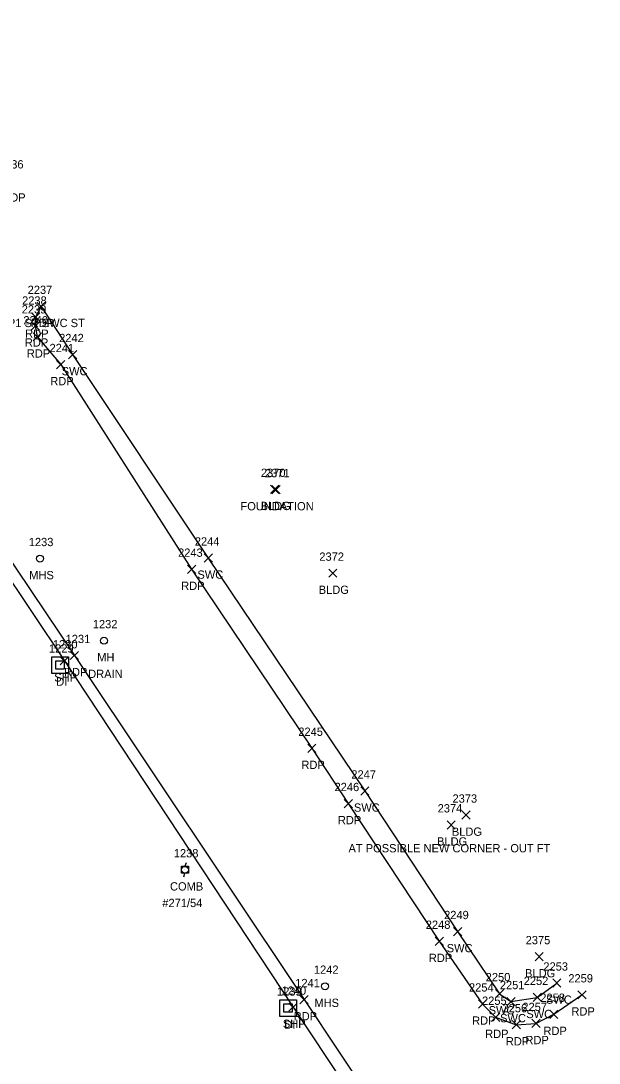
# Model space of a CAD drawing. Extents: x 1635588 to 1637550, y 621583 to 623638.
# Drawn here: x 1636634.9 to 1636774.5, y 622685.3 to 622937 of the extents above; entities that cross this region are included whole.
import ezdxf

# ---------------------------------------------------------------- set-up
doc = ezdxf.new("R2010")
doc.units = 0
for name, color, linetype in [('D_A', 7, 'Continuous'), ('D_I', 7, 'Continuous'), ('DS', 7, 'Continuous'), ('L_A', 7, 'Continuous'), ('L_C', 7, 'Continuous'), ('L_I', 7, 'Continuous'), ('L_TIC', 7, 'Continuous'), ('P_A', 7, 'Continuous'), ('P_I', 7, 'Continuous'), ('P_TIC', 7, 'Continuous'), ('PET', 7, 'Continuous'), ('PSP', 7, 'Continuous'), ('R_A', 7, 'Continuous'), ('R_I', 7, 'Continuous'), ('R_TIC', 7, 'Continuous'), ('RSW', 7, 'Continuous'), ('U_A', 7, 'Continuous'), ('U_C', 7, 'Continuous'), ('U_I', 7, 'Continuous'), ('UP', 7, 'Continuous'), ('USMH', 7, 'Continuous'), ('UUMH', 7, 'Continuous')]:
    doc.layers.add(name, color=color, linetype=linetype)

msp = doc.modelspace()

# ---------------------------------------------------------------- linework, layer by layer
at = {"layer": 'DS'}
for p, q in [((1636642.34, 622783.45), (1636646.34, 622783.45)), ((1636642.34, 622779.45), (1636642.34, 622783.45)), ((1636643.34, 622780.45), (1636643.34, 622782.45)), ((1636643.34, 622782.45), (1636645.34, 622782.45)), ((1636644.35, 622781.45), (1636644.35, 622781.45)), ((1636644.35, 622781.45), (1636644.35, 622781.45)), ((1636645.34, 622782.45), (1636645.34, 622780.45)), ((1636646.34, 622783.45), (1636646.34, 622779.45)), ((1636646.34, 622779.45), (1636642.34, 622779.45)), ((1636645.34, 622780.45), (1636643.34, 622780.45)), ((1636697.41, 622700.63), (1636701.41, 622700.63)), ((1636697.41, 622696.63), (1636697.41, 622700.63)), ((1636701.41, 622700.63), (1636701.41, 622696.63)), ((1636698.41, 622697.63), (1636698.41, 622699.63)), ((1636698.41, 622699.63), (1636700.41, 622699.63)), ((1636699.42, 622698.63), (1636699.42, 622698.63)), ((1636699.42, 622698.63), (1636699.42, 622698.63)), ((1636700.41, 622699.63), (1636700.41, 622697.63)), ((1636701.41, 622696.63), (1636697.41, 622696.63)), ((1636700.41, 622697.63), (1636698.41, 622697.63))]:
    msp.add_line(p, q, dxfattribs=at)
at = {"layer": 'L_TIC'}
for points in [[(1636695.17, 622822.87), (1636697.17, 622824.87)], [(1636697.17, 622822.87), (1636695.17, 622824.87)], [(1636695.5, 622822.8), (1636697.5, 622824.8)], [(1636697.5, 622822.8), (1636695.5, 622824.8)], [(1636709.21, 622802.63), (1636711.21, 622804.63)], [(1636711.21, 622802.63), (1636709.21, 622804.63)], [(1636741.36, 622744.23), (1636743.36, 622746.23)], [(1636743.36, 622744.23), (1636741.36, 622746.23)], [(1636737.78, 622741.87), (1636739.78, 622743.87)], [(1636739.78, 622741.87), (1636737.78, 622743.87)], [(1636759.04, 622710.05), (1636761.04, 622712.05)], [(1636761.04, 622710.05), (1636759.04, 622712.05)]]:
    msp.add_lwpolyline(points, dxfattribs=at)
at = {"layer": 'P_TIC'}
for points in [[(1636638.76, 622867.04), (1636640.76, 622869.04)], [(1636640.76, 622867.04), (1636638.76, 622869.04)], [(1636637.34, 622862.33), (1636639.34, 622864.33)], [(1636639.34, 622862.33), (1636637.34, 622864.33)], [(1636637.42, 622864.46), (1636639.42, 622866.46)], [(1636639.42, 622864.46), (1636637.42, 622866.46)], [(1636637.81, 622859.69), (1636639.81, 622861.69)], [(1636639.81, 622859.69), (1636637.81, 622861.69)], [(1636643.48, 622853), (1636645.48, 622855)], [(1636645.48, 622853), (1636643.48, 622855)], [(1636675.09, 622803.59), (1636677.09, 622805.59)], [(1636677.09, 622803.59), (1636675.09, 622805.59)], [(1636646.79, 622782.76), (1636648.79, 622784.76)], [(1636648.79, 622782.76), (1636646.79, 622784.76)], [(1636644.38, 622781.47), (1636646.38, 622783.47)], [(1636646.38, 622781.47), (1636644.38, 622783.47)], [(1636704.13, 622760.36), (1636706.13, 622762.36)], [(1636706.13, 622760.36), (1636704.13, 622762.36)], [(1636712.93, 622747.02), (1636714.93, 622749.02)], [(1636714.93, 622747.02), (1636712.93, 622749.02)], [(1636734.91, 622713.76), (1636736.91, 622715.76)], [(1636736.91, 622713.76), (1636734.91, 622715.76)], [(1636702.25, 622699.68), (1636704.25, 622701.68)], [(1636704.25, 622699.68), (1636702.25, 622701.68)], [(1636745.35, 622698.62), (1636747.35, 622700.62)], [(1636747.35, 622698.62), (1636745.35, 622700.62)], [(1636769.35, 622700.83), (1636771.35, 622702.83)], [(1636771.35, 622700.83), (1636769.35, 622702.83)], [(1636699.61, 622697.86), (1636701.61, 622699.86)], [(1636701.61, 622697.86), (1636699.61, 622699.86)], [(1636762.58, 622696.14), (1636764.58, 622698.14)], [(1636764.58, 622696.14), (1636762.58, 622698.14)], [(1636748.5, 622695.42), (1636750.5, 622697.42)], [(1636750.5, 622695.42), (1636748.5, 622697.42)], [(1636753.5, 622693.62), (1636755.5, 622695.62)], [(1636755.5, 622693.62), (1636753.5, 622695.62)], [(1636758.24, 622693.92), (1636760.24, 622695.92)], [(1636760.24, 622693.92), (1636758.24, 622695.92)]]:
    msp.add_lwpolyline(points, dxfattribs=at)
at = {"layer": 'PET'}
for points in [[(1636496.54, 623045.3), (1636533.69, 622970.65), (1636546.95, 622944.69), (1636557.06, 622926.23), (1636579, 622887.89), (1636603.72, 622849.48), (1636616.07, 622830.82), (1636647.79, 622783.76), (1636703.25, 622700.68), (1636737.08, 622649.81), (1636763.83, 622609.67), (1636812.95, 622535.62), (1636858.06, 622468.21), (1636878.24, 622438.26), (1636911.18, 622389.38), (1636974.88, 622293.33), (1636986.61, 622276.7), (1637016.63, 622231.99)], [(1636639.76, 622868.04), (1636638.42, 622865.46), (1636638.34, 622863.33), (1636638.81, 622860.69), (1636644.48, 622854), (1636676.09, 622804.59), (1636705.13, 622761.36), (1636713.93, 622748.02), (1636735.91, 622714.76), (1636746.35, 622699.62), (1636749.5, 622696.42), (1636754.5, 622694.62), (1636759.24, 622694.92), (1636763.58, 622697.14), (1636770.35, 622701.83)]]:
    msp.add_lwpolyline(points, dxfattribs=at)
at = {"layer": 'PSP'}
msp.add_lwpolyline([(1636412.61, 623220.07), (1636436.6, 623167.3), (1636456.23, 623125.07), (1636460.67, 623115.98), (1636475.52, 623084.87), (1636494.51, 623045.42), (1636524.16, 622986.51), (1636530.74, 622972.24), (1636554.07, 622925.3), (1636577.18, 622886.3), (1636601.72, 622847.41), (1636613.46, 622830.09), (1636645.38, 622782.47), (1636700.61, 622698.86), (1636734.28, 622648.07), (1636752.12, 622619.3), (1636752.46, 622616.81), (1636755.34, 622613.42), (1636810.04, 622534.39), (1636855.63, 622465.66), (1636874.76, 622437.49), (1636904.15, 622393.55)], dxfattribs=at)
at = {"layer": 'R_TIC'}
for points in [[(1636638.76, 622867.04), (1636640.76, 622869.04)], [(1636640.76, 622867.04), (1636638.76, 622869.04)], [(1636646.36, 622855.41), (1636648.36, 622857.41)], [(1636648.36, 622855.41), (1636646.36, 622857.41)], [(1636679.13, 622806.29), (1636681.13, 622808.29)], [(1636681.13, 622806.29), (1636679.13, 622808.29)], [(1636716.94, 622750.05), (1636718.94, 622752.05)], [(1636718.94, 622750.05), (1636716.94, 622752.05)], [(1636739.35, 622716.11), (1636741.35, 622718.11)], [(1636741.35, 622716.11), (1636739.35, 622718.11)], [(1636763.31, 622703.68), (1636765.31, 622705.68)], [(1636765.31, 622703.68), (1636763.31, 622705.68)], [(1636749.48, 622701.11), (1636751.48, 622703.11)], [(1636751.48, 622701.11), (1636749.48, 622703.11)], [(1636752.23, 622699.2), (1636754.23, 622701.2)], [(1636754.23, 622699.2), (1636752.23, 622701.2)], [(1636758.57, 622700.21), (1636760.57, 622702.21)], [(1636760.57, 622700.21), (1636758.57, 622702.21)]]:
    msp.add_lwpolyline(points, dxfattribs=at)
at = {"layer": 'RSW'}
msp.add_lwpolyline([(1636639.76, 622868.04), (1636647.36, 622856.41), (1636680.13, 622807.29), (1636717.94, 622751.05), (1636740.35, 622717.11), (1636750.48, 622702.11), (1636753.23, 622700.2), (1636759.57, 622701.21), (1636764.31, 622704.68)], dxfattribs=at)
at = {"layer": 'UP'}
for p, q in [((1636674.75, 622733.69), (1636674.5, 622732.86)), ((1636673.66, 622731.19), (1636673.66, 622732.86)), ((1636673.66, 622732.86), (1636675.33, 622732.86)), ((1636675.33, 622731.19), (1636673.66, 622731.19)), ((1636674.25, 622730.36), (1636674.5, 622731.19)), ((1636674.5, 622732.02), (1636674.5, 622732.02)), ((1636675.33, 622732.86), (1636675.33, 622731.19))]:
    msp.add_line(p, q, dxfattribs=at)
msp.add_circle((1636674.5, 622732.02), 0.833, dxfattribs=at)
at = {"layer": 'USMH'}
for p, q in [((1636639.47, 622807.16), (1636639.47, 622807.16)), ((1636640.3, 622807.16), (1636640.3, 622807.16)), ((1636708.33, 622703.91), (1636708.33, 622703.91)), ((1636709.17, 622703.91), (1636709.17, 622703.91))]:
    msp.add_line(p, q, dxfattribs=at)
for centre in [(1636639.47, 622807.16), (1636708.33, 622703.91)]:
    msp.add_circle(centre, 0.833, dxfattribs=at)
at = {"layer": 'UUMH'}
for p, q in [((1636654.94, 622787.33), (1636654.94, 622787.33)), ((1636655.77, 622787.33), (1636655.77, 622787.33))]:
    msp.add_line(p, q, dxfattribs=at)
msp.add_circle((1636654.94, 622787.33), 0.833, dxfattribs=at)

# ---------------------------------------------------------------- texts
at = {"layer": 'D_A'}
for p in [(1636643.4, 622776.45), (1636698.47, 622693.63)]:
    msp.add_text('DI', height=2, dxfattribs=at).set_placement(p)
at = {"layer": 'D_I'}
for s, p in [('1229', (1636641.65, 622784.45)), ('1239', (1636696.72, 622701.63))]:
    msp.add_text(s, height=2, dxfattribs=at).set_placement(p)
at = {"layer": 'L_A'}
for s, p in [('FOUNDATION', (1636687.9, 622818.8)), ('BLDG', (1636692.76, 622818.87)), ('BLDG', (1636706.8, 622798.63)), ('BLDG', (1636738.95, 622740.23)), ('BLDG', (1636735.37, 622737.87)), ('BLDG', (1636756.63, 622706.05))]:
    msp.add_text(s, height=2, dxfattribs=at).set_placement(p)
at = {"layer": 'L_C'}
msp.add_text('AT POSSIBLE NEW CORNER - OUT FT', height=2, dxfattribs=at).set_placement((1636713.99, 622736.23))
at = {"layer": 'L_I'}
for s, p in [('2370', (1636692.83, 622826.87)), ('2371', (1636693.81, 622826.8)), ('2372', (1636706.95, 622806.63)), ('2373', (1636739.1, 622748.23)), ('2374', (1636735.52, 622745.87)), ('2375', (1636756.78, 622714.05))]:
    msp.add_text(s, height=2, dxfattribs=at).set_placement(p)
at = {"layer": 'P_A'}
for s, p in [('RDP', (1636630.36, 622893.34)), ('RDP', (1636637.25, 622863.04)), ('RDP', (1636635.91, 622860.46)), ('RDP', (1636635.83, 622858.33)), ('RDP', (1636636.3, 622855.69)), ('RDP', (1636641.97, 622849)), ('RDP', (1636673.58, 622799.59)), ('SHP', (1636642.92, 622777.47)), ('RDP', (1636645.28, 622778.76)), ('RDP', (1636702.62, 622756.36)), ('RDP', (1636711.42, 622743.02)), ('RDP', (1636733.39, 622709.76)), ('RDP', (1636767.83, 622696.83)), ('SHP', (1636698.14, 622693.86)), ('RDP', (1636700.74, 622695.68)), ('RDP', (1636743.84, 622694.62)), ('RDP', (1636746.99, 622691.42)), ('RDP', (1636761.07, 622692.14)), ('RDP', (1636751.99, 622689.62)), ('RDP', (1636756.72, 622689.92))]:
    msp.add_text(s, height=2, dxfattribs=at).set_placement(p)
at = {"layer": 'P_I'}
for s, p in [('2236', (1636629.56, 622901.34)), ('2237', (1636636.5, 622871.04)), ('2238', (1636635.16, 622868.46)), ('2239', (1636635.07, 622866.33)), ('2240', (1636635.47, 622863.69)), ('2241', (1636641.79, 622857)), ('2243', (1636672.83, 622807.59)), ('1231', (1636645.67, 622786.76)), ('1230', (1636642.6, 622785.47)), ('2245', (1636701.87, 622764.36)), ('2246', (1636710.62, 622751.02)), ('2248', (1636732.65, 622717.76)), ('1241', (1636701.13, 622703.68)), ('2259', (1636767.08, 622704.83)), ('1240', (1636697.83, 622701.86)), ('2254', (1636743.09, 622702.62)), ('2255', (1636746.24, 622699.42)), ('2258', (1636760.32, 622700.14)), ('2256', (1636751.19, 622697.62)), ('2257', (1636755.98, 622697.92))]:
    msp.add_text(s, height=2, dxfattribs=at).set_placement(p)
at = {"layer": 'R_A'}
for s, p in [('RDP1 ST SWC ST', (1636627.87, 622863.04)), ('SWC', (1636644.72, 622851.41)), ('SWC', (1636677.5, 622802.29)), ('SWC', (1636715.3, 622746.05)), ('SWC', (1636737.71, 622712.11)), ('SWC', (1636761.68, 622699.68)), ('SWC', (1636747.84, 622697.11)), ('SWC', (1636756.93, 622696.21)), ('SWC', (1636750.6, 622695.2))]:
    msp.add_text(s, height=2, dxfattribs=at).set_placement(p)
at = {"layer": 'R_I'}
for s, p in [('2237', (1636636.5, 622871.04)), ('2242', (1636644.1, 622859.41)), ('2244', (1636676.87, 622810.29)), ('2247', (1636714.68, 622754.05)), ('2249', (1636737.08, 622720.11)), ('2253', (1636761.05, 622707.68)), ('2250', (1636747.13, 622705.11)), ('2252', (1636756.31, 622704.21)), ('2251', (1636750.54, 622703.2))]:
    msp.add_text(s, height=2, dxfattribs=at).set_placement(p)
at = {"layer": 'U_A'}
for s, p in [('MHS', (1636636.88, 622802.16)), ('MH', (1636653.3, 622782.33)), ('COMB', (1636670.88, 622727.02)), ('MHS', (1636705.75, 622698.91))]:
    msp.add_text(s, height=2, dxfattribs=at).set_placement(p)
at = {"layer": 'U_C'}
for s, p in [('DRAIN', (1636651.12, 622778.33)), ('#271/54', (1636669.03, 622723.02))]:
    msp.add_text(s, height=2, dxfattribs=at).set_placement(p)
at = {"layer": 'U_I'}
for s, p in [('1233', (1636636.77, 622810.16)), ('1232', (1636652.24, 622790.33)), ('1238', (1636671.8, 622735.02)), ('1242', (1636705.64, 622706.91))]:
    msp.add_text(s, height=2, dxfattribs=at).set_placement(p)

doc.saveas('drawing.dxf')
